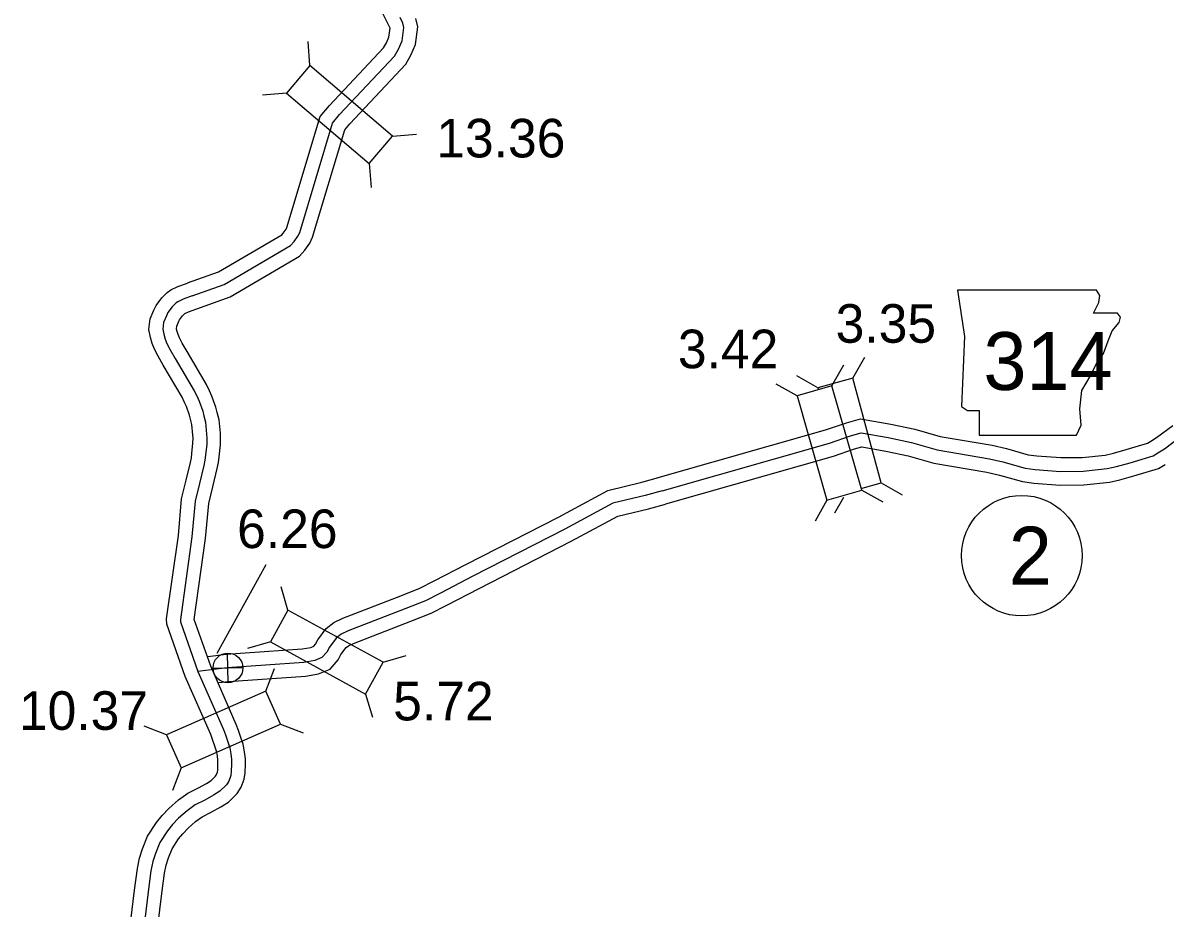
# Model space of a CAD drawing. Extents: x -83719 to 153526, y -11835 to 11446.
# Drawn here: x -3355.1 to -2938.4, y -1506.8 to -1183.7 of the extents above; entities that cross this region are included whole.
import ezdxf

# ---------------------------------------------------------------- set-up
doc = ezdxf.new("R2010")
doc.units = 0
for name, color, linetype in [('Level 10', 7, 'Continuous'), ('Level 11', 7, 'Continuous'), ('Level 20', 7, 'Continuous'), ('Level 21', 7, 'Continuous'), ('Level 25', 7, 'Continuous'), ('Level 26', 7, 'Continuous'), ('Level 27', 7, 'Continuous'), ('Level 58', 7, 'Continuous'), ('Level 59', 7, 'Continuous')]:
    doc.layers.add(name, color=color, linetype=linetype)

msp = doc.modelspace()

# ---------------------------------------------------------------- linework, layer by layer
at = {"layer": 'Level 10'}
for points in [[(-3295.02, -1278.63), (-3283.76, -1274.6), (-3260.68, -1261.09), (-3260.13, -1260.45), (-3259.09, -1259.01), (-3258.79, -1258.37), (-3246.7, -1217.81), (-3243.31, -1213.84), (-3223.54, -1192.81), (-3222.5, -1190.97), (-3221.58, -1188.91), (-3221.18, -1185.64), (-3221.25, -1185.36), (-3221.93, -1183.88), (-3224.13, -1179.5)], [(-3291.65, -1288.05), (-3279.52, -1283.7), (-3254.17, -1268.87), (-3252.27, -1266.64), (-3250.45, -1264.12), (-3249.43, -1261.96), (-3237.72, -1222.69), (-3235.86, -1220.51), (-3215.44, -1198.79), (-3213.56, -1195.48), (-3211.83, -1191.6), (-3211.05, -1185.12), (-3211.73, -1182.13)], [(-3319.61, -1543.53), (-3314.35, -1500.21), (-3313.34, -1492.32), (-3312.52, -1488.57), (-3311.49, -1485.12), (-3309.6, -1480.54), (-3306.4, -1475.57), (-3304.25, -1473.01), (-3301.83, -1470.44), (-3298.36, -1467.32), (-3294.88, -1464.83), (-3291.04, -1462.94), (-3288.09, -1461.28), (-3286.37, -1460.18), (-3284.79, -1458.65), (-3284.56, -1458.27), (-3284.17, -1457.19), (-3284.05, -1456.42), (-3283.95, -1453.99), (-3283.95, -1452.84), (-3284.14, -1451.24), (-3284.48, -1449.49), (-3285.05, -1447.72), (-3285.91, -1445.21), (-3286.54, -1443.46), (-3295.9, -1422.23), (-3302.64, -1403.15), (-3302.68, -1401.21), (-3298.4, -1370.75), (-3297.2, -1357.44), (-3295.57, -1350.64), (-3293.99, -1344.2), (-3293.65, -1342.42), (-3293.42, -1340.89), (-3293.06, -1337.14), (-3293.01, -1335.32), (-3293.06, -1334.15), (-3293.43, -1330.28), (-3293.91, -1328.31), (-3294.28, -1326.9), (-3295.42, -1323.71), (-3296.11, -1322.23), (-3297.01, -1320.36), (-3303.88, -1308.65), (-3305.73, -1305.39), (-3307.1, -1302.79), (-3307.9, -1300.74), (-3308.59, -1298.55), (-3309.19, -1295.64), (-3308.63, -1291.76), (-3307.36, -1288.54), (-3306.52, -1286.84), (-3304.47, -1284.07), (-3302.44, -1282.05), (-3301.1, -1281.14), (-3298.62, -1279.93), (-3295.03, -1278.64)], [(-3309.73, -1545.18), (-3304.43, -1501.45), (-3303.48, -1494.03), (-3302.83, -1491.08), (-3302.05, -1488.47), (-3300.7, -1485.19), (-3298.34, -1481.51), (-3296.78, -1479.66), (-3294.84, -1477.6), (-3292.09, -1475.13), (-3289.73, -1473.44), (-3286.38, -1471.79), (-3282.95, -1469.86), (-3280.13, -1468.07), (-3276.88, -1464.9), (-3275.5, -1462.59), (-3274.44, -1459.7), (-3274.08, -1457.39), (-3273.95, -1454.2), (-3273.95, -1452.28), (-3274.25, -1449.69), (-3274.79, -1446.98), (-3275.56, -1444.57), (-3276.47, -1441.91), (-3277.25, -1439.75), (-3286.6, -1418.54), (-3292.62, -1401.5), (-3288.46, -1371.9), (-3287.31, -1359.06), (-3285.85, -1352.99), (-3284.23, -1346.35), (-3283.79, -1344.12), (-3283.49, -1342.1), (-3283.07, -1337.75), (-3283, -1335.24), (-3283.08, -1333.47), (-3283.54, -1328.61), (-3284.21, -1325.86), (-3284.71, -1323.95), (-3286.17, -1319.91), (-3287.07, -1317.95), (-3288.18, -1315.65), (-3295.22, -1303.66), (-3296.95, -1300.58), (-3297.99, -1298.62), (-3298.46, -1297.42), (-3298.9, -1296.03), (-3299.04, -1295.34), (-3298.9, -1294.34), (-3298.2, -1292.58), (-3297.94, -1292.06), (-3296.88, -1290.63), (-3296.05, -1289.8), (-3294.72, -1289.15), (-3291.65, -1288.05)]]:
    msp.add_lwpolyline(points, dxfattribs=at)
at = {"layer": 'Level 11'}
for points in [[(-3123.32, -1349.67), (-3062.36, -1332.28), (-3054.69, -1329.66), (-3049.53, -1328.25), (-3038.44, -1330.14), (-3029.67, -1332.01), (-3020.5, -1334.68), (-3001.45, -1337.85), (-2996.32, -1339.06), (-2988.38, -1341.31), (-2985.25, -1341.75), (-2976.42, -1342.38), (-2968.63, -1342.27), (-2960.3, -1341.42), (-2957.29, -1340.78), (-2952.61, -1339.44), (-2944.83, -1337.11), (-2943.67, -1336.41), (-2941.52, -1335), (-2935.64, -1330.6)], [(-3120.58, -1359.28), (-3059.37, -1341.83), (-3051.75, -1339.22), (-3049.03, -1338.48), (-3040.33, -1339.96), (-3032.11, -1341.72), (-3022.73, -1344.45), (-3003.42, -1347.66), (-2998.84, -1348.74), (-2990.44, -1351.13), (-2986.29, -1351.7), (-2976.71, -1352.39), (-2968.05, -1352.26), (-2958.75, -1351.31), (-2954.87, -1350.49), (-2949.8, -1349.04), (-2940.76, -1346.32), (-2938.36, -1344.88)], [(-3287.62, -1414.91), (-3281.01, -1414.1), (-3253.22, -1412.15), (-3250.04, -1411.61), (-3249.02, -1411.19), (-3248.36, -1410.43), (-3247.5, -1408.86), (-3244.41, -1404.71), (-3241.64, -1402.51), (-3238.38, -1400.97), (-3217.19, -1392.77), (-3210.28, -1390.06), (-3205.11, -1387.38), (-3193.24, -1381.21), (-3159.73, -1364.07), (-3141.67, -1354.35), (-3129.36, -1351.32), (-3123.27, -1349.65)], [(-3283.67, -1424.5), (-3280.05, -1424.06), (-3252.03, -1422.09), (-3247.25, -1421.28), (-3243.04, -1419.53), (-3240.13, -1416.21), (-3239.06, -1414.28), (-3237.16, -1411.73), (-3236.32, -1411.05), (-3234.44, -1410.16), (-3213.56, -1402.09), (-3206.14, -1399.18), (-3200.5, -1396.25), (-3188.66, -1390.09), (-3155.09, -1372.92), (-3138.05, -1363.76), (-3126.85, -1361), (-3120.63, -1359.3)]]:
    msp.add_lwpolyline(points, dxfattribs=at)
at = {"layer": 'Level 20'}
for p, q in [((-3250.37, -1199.3), (-3251.07, -1190.53)), ((-3258.94, -1209.35), (-3267.71, -1210.04)), ((-3220.24, -1225), (-3211.47, -1224.3)), ((-3228.81, -1235.04), (-3228.11, -1243.82)), ((-3059.95, -1316.2), (-3055.67, -1308.51)), ((-3052.37, -1313.37), (-3048.01, -1305.73)), ((-3065.11, -1316.84), (-3072.75, -1312.47)), ((-3072.64, -1319.82), (-3080.34, -1315.55)), ((-3052.37, -1313.37), (-3065.11, -1316.84)), ((-3065.11, -1316.84), (-3064.88, -1317.65)), ((-3041.95, -1351.57), (-3052.37, -1313.37)), ((-3049.09, -1354.28), (-3041.4, -1358.56)), ((-3048.94, -1353.48), (-3041.95, -1351.57)), ((-3041.95, -1351.57), (-3034.31, -1355.94)), ((-3061.78, -1357.9), (-3066.06, -1365.59)), ((-3055.77, -1356.94), (-3059.05, -1362.68)), ((-3258.42, -1398), (-3260.87, -1389.55)), ((-3264.77, -1409.57), (-3273.22, -1412.02)), ((-3223.71, -1417.08), (-3215.26, -1414.62)), ((-3266.44, -1427.57), (-3263.26, -1419.37)), ((-3230.07, -1428.65), (-3227.62, -1437.1)), ((-3302.67, -1443.56), (-3310.87, -1440.37)), ((-3261.11, -1439.65), (-3252.91, -1442.83)), ((-3297.34, -1455.63), (-3300.52, -1463.84))]:
    msp.add_line(p, q, dxfattribs=at)
for points in [[(-3258.94, -1209.35), (-3228.81, -1235.04), (-3220.24, -1225), (-3250.37, -1199.3)], [(-3072.64, -1319.82), (-3061.78, -1357.9), (-3049.09, -1354.28), (-3059.95, -1316.2)], [(-3223.71, -1417.08), (-3258.42, -1398), (-3264.77, -1409.57), (-3230.07, -1428.65)], [(-3266.44, -1427.57), (-3302.67, -1443.56), (-3297.34, -1455.63), (-3261.11, -1439.65)]]:
    msp.add_lwpolyline(points, close=True, dxfattribs=at)
at = {"layer": 'Level 21'}
msp.add_lwpolyline([(-3014.13, -1281.19), (-3011.59, -1298.1), (-3012.72, -1323.76), (-3010.46, -1325.17), (-3006.23, -1325.17), (-3006.23, -1334.2), (-2970.7, -1334.2), (-2969.01, -1330.53), (-2969.57, -1324.61), (-2968.73, -1317.84), (-2965.63, -1312.48), (-2963.65, -1308.54), (-2960.83, -1304.31), (-2959.14, -1299.8), (-2957.73, -1296.13), (-2955.19, -1293.03), (-2954.63, -1291.05), (-2955.76, -1289.64), (-2964.5, -1289.64), (-2962.53, -1285.7), (-2962.24, -1283.16), (-2963.41, -1281.21)], close=True, dxfattribs=at)
at = {"layer": 'Level 25'}
for p, q in [((-3065.11, -1316.84), (-3064.88, -1317.65)), ((-3266.51, -1381.45), (-3284.31, -1413.84))]:
    msp.add_line(p, q, dxfattribs=at)
at = {"layer": 'Level 26'}
for p, q in [((-3280.17, -1424.56), (-3280.43, -1413.71)), ((-3285.72, -1419.26), (-3274.88, -1419.01))]:
    msp.add_line(p, q, dxfattribs=at)
msp.add_circle((-3280.3, -1419.13), 5.43, dxfattribs=at)
at = {"layer": 'Level 27'}
msp.add_circle((-2990.69, -1378.15), 22, dxfattribs=at)
at = {"layer": 'Level 58'}
msp.add_line((-3065.11, -1316.84), (-3064.88, -1317.65), dxfattribs=at)
at = {"layer": 'Level 59'}
for points in [[(-3293.34, -1283.34), (-3281.64, -1279.15), (-3257.43, -1264.98), (-3256.2, -1263.54), (-3254.77, -1261.57), (-3254.11, -1260.16), (-3242.21, -1220.25), (-3239.59, -1217.17), (-3219.49, -1195.8), (-3218.03, -1193.23), (-3216.71, -1190.25), (-3216.12, -1185.38), (-3216.49, -1183.74), (-3217.42, -1181.71)], [(-3293.34, -1283.34), (-3296.67, -1284.54), (-3298.58, -1285.48), (-3299.24, -1285.92), (-3300.68, -1287.35), (-3302.23, -1289.45), (-3302.78, -1290.56), (-3303.76, -1293.05), (-3304.11, -1295.49), (-3303.75, -1297.29), (-3303.18, -1299.08), (-3302.55, -1300.7), (-3301.34, -1302.98), (-3299.55, -1306.16), (-3292.6, -1318.01), (-3291.59, -1320.09), (-3290.8, -1321.81), (-3289.49, -1325.43), (-3289.06, -1327.09), (-3288.49, -1329.44), (-3288.07, -1333.81), (-3288.01, -1335.28), (-3288.06, -1337.45), (-3288.45, -1341.49), (-3288.72, -1343.27), (-3289.11, -1345.28), (-3290.71, -1351.82), (-3292.25, -1358.25), (-3293.43, -1371.33), (-3297.67, -1401.51), (-3297.66, -1402.25), (-3291.25, -1420.39), (-3281.89, -1441.6), (-3281.19, -1443.56), (-3280.31, -1446.15), (-3279.63, -1448.24), (-3279.19, -1450.46), (-3278.95, -1452.56), (-3278.95, -1454.1), (-3279.07, -1456.9), (-3279.3, -1458.44), (-3280.03, -1460.43), (-3280.84, -1461.78), (-3283.25, -1464.13), (-3285.52, -1465.57), (-3288.71, -1467.37), (-3292.3, -1469.14), (-3295.22, -1471.23), (-3298.33, -1474.02), (-3300.52, -1476.33), (-3302.37, -1478.54), (-3305.15, -1482.86), (-3306.77, -1486.8), (-3307.67, -1489.82), (-3308.41, -1493.17), (-3309.39, -1500.83), (-3314.67, -1544.36)], [(-3121.95, -1354.48), (-3060.87, -1337.05), (-3053.22, -1334.44), (-3049.28, -1333.36), (-3039.39, -1335.05), (-3030.89, -1336.86), (-3021.61, -1339.57), (-3002.43, -1342.75), (-2997.58, -1343.9), (-2989.41, -1346.22), (-2985.77, -1346.72), (-2976.56, -1347.39), (-2968.34, -1347.27), (-2959.53, -1346.37), (-2956.08, -1345.64), (-2951.21, -1344.24), (-2942.79, -1341.71), (-2941.02, -1340.64), (-2938.65, -1339.1), (-2933.07, -1334.92)], [(-3121.95, -1354.48), (-3128.11, -1356.16), (-3139.86, -1359.05), (-3157.41, -1368.5), (-3190.95, -1385.65), (-3202.81, -1391.82), (-3208.21, -1394.62), (-3215.37, -1397.43), (-3236.41, -1405.57), (-3238.98, -1406.78), (-3240.78, -1408.22), (-3243.28, -1411.57), (-3244.24, -1413.32), (-3246.03, -1415.36), (-3248.64, -1416.44), (-3252.62, -1417.12), (-3280.53, -1419.08), (-3291.25, -1420.39)]]:
    msp.add_lwpolyline(points, dxfattribs=at)

# ---------------------------------------------------------------- texts
at = {"layer": 'Level 21'}
msp.add_text('314', height=21.12, dxfattribs=at).set_placement((-3004.69, -1317.68))
at = {"layer": 'Level 25'}
msp.add_text('6.26', height=14.08, dxfattribs=at).set_placement((-3276.96, -1375.39))
at = {"layer": 'Level 27'}
msp.add_text('2', height=21.12, dxfattribs=at).set_placement((-2995.42, -1388.71))
at = {"layer": 'Level 58'}
for s, p in [('13.36', (-3204.3, -1232.8)), ('3.35', (-3058.6, -1300.44)), ('3.42', (-3116.15, -1309.74)), ('5.72', (-3220.02, -1438.28)), ('10.37', (-3356.56, -1441.73))]:
    msp.add_text(s, height=14.08, dxfattribs=at).set_placement(p)

doc.saveas('drawing.dxf')
